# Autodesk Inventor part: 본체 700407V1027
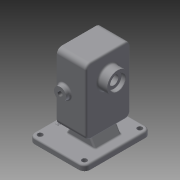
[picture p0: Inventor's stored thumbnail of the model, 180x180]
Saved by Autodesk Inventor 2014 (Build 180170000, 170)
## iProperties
Created: 2020-04
Part Number: 본체 700407V1027
Material: 일반
Document SubType Name: Modeling
Designer: kh
Density: 1 g/cm^3
Appearance: 기본값
Mass: 545.034 g
Surface Area: 818.916 cm^2
Volume: 545.034 cm^3
Author: kh
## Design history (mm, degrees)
sketch "스케치1"
  geometry: L1 (-50, -60)-(50, -60); L2 (50, -60)-(50, 60); L3 (50, 60)-(-50, 60); L4 (-50, 60)-(-50, -60); L5 (-50, -60)-(50, 60); L6 (50, -60)-(-50, 60); 1 further point
  constraints: 12 end point, 2 midpoint, 2 parallel, 1 horizontal, 1 perpendicular
  dimensions: "d0" = 100 distance of L2.end L3.end; "d1" = 120 distance of L3.end L1.start
extrude "돌출1" new body sketch "스케치1" distance "d2" = 10; taper "d3" = 0 deg
node "작업 평면2"
  node "작업 평면1"
sketch "스케치2"
  geometry: L1 (20, 150)-(100, 150); L2 (100, 150)-(100, 30); L3 (100, 30)-(20, 30); L4 (20, 30)-(20, 150); L5 (120, 0)-(0, 0) reference; L6 (20, 90)-(100, 90); L7 (60, 0)-(60, 50.718)
  constraints: 12 end point, 2 midpoint, 2 parallel, 2 perpendicular, 1 horizontal, 1 other
  dimensions: "d5" = 80 distance of L1.start L1.end; "d6" = 150 distance between parallel lines of L5 L1; "d7" = 90 distance from line of L7.start L6
extrude "돌출2" join sketch "스케치2" distance "d8" = 53; taper "d9" = 0 deg
sketch "스케치3"
  geometry: L1 (150, 20)-(150, 100) reference; L2 (150, 100)-(30, 100) reference; L3 (30, 100)-(30, 20) reference; L4 (30, 20)-(150, 20) reference; L5 (112, 60)-(68, 60); L6 (112, 36)-(68, 36); L7 (68, 84)-(112, 84); L8 (150, 100)-(30, 100) reference; L9 (90, 100)-(90, 20); A1 r 24 centre (112, 60) between (112, 36) and (112, 84); A2 r 24 centre (68, 60) between (68, 84) and (68, 36); 3 further points
  constraints: 10 end point, 4 midpoint, 4 point on circle, 4 tangent, 2 centre point, 2 parallel, 1 coincident
  dimensions: "d10" = 92 dimension on A2 A1; "d11" = 24 radius of A1
extrude "돌출3" cut sketch "스케치3" distance "d12" = 29; taper "d13" = 0 deg
sketch "스케치4"
  geometry: L1 (-150, 20)-(-150, 100) reference; L2 (-30, 20)-(-150, 20) reference; L3 (-30, 100)-(-30, 20) reference; L4 (-150, 100)-(-30, 100) reference; L5 (-150, 60)-(-30, 60); L6 (-30, 100)-(-30, 20) reference; L7 (-90, 20)-(-90, 118.269); L8 (-150, 100)-(-30, 100) reference; C1 r 19 at (-112, 60); 1 further point
  constraints: 4 end point, 3 midpoint, 1 centre point, 1 perpendicular, 1 point on line
  dimensions: "d14" = 38 diameter of C1; "d15" = 22 distance from line of L7 C1.centre
extrude "돌출4" join sketch "스케치4" distance "d16" = 17; taper "d17" = 0 deg
sketch "스케치5"
  geometry: L1 (112, 36)-(68, 36) reference; L2 (68, 84)-(112, 84) reference; A1 r 24 centre (112, 60) between (112, 36) and (112, 84) reference; A2 r 24 centre (68, 60) between (68, 84) and (68, 36) reference; 1 further point
hole "구멍1" sketch "스케치5" at (112, 60), (68, 60) diameter "d18" = 25; stored, may be unused: countersink angle "d22" = 90 deg, drill point angle "d24" = 0 deg; dims "d19" = 6, "d20" = 4, "d21" = 2, "d23" = 15
sketch "스케치6"
  geometry: C1 r 12.5 at (0, 0) reference; C2 r 8.5 at (0, 0); 1 further point
  constraints: 1 centre point, 1 coincident
  dimensions: "d25" = 17 diameter of C2
extrude "돌출5" cut sketch "스케치6" stored distance "d26" = 17; taper "d27" = 0 deg
sketch "스케치7"
  geometry: L1 (-33, 30)-(20, 30) reference; L2 (50, 10)-(-50, 10) reference; L3 (-21.453, 30)-(-33, 10); L4 (-50, 10)-(50, 10) reference; L5 (8.453, 30)-(20, 10); L6 (8.453, 30)-(-21.453, 30); L7 (-33, 30)-(20, 30) reference; L8 (20, 10)-(-33, 10); 1 further point
  constraints: 8 end point, 4 point on line, 2 collinear
  dimensions: "d28" = 60 deg angle of L4 L3; "d29" = 60 deg angle of L2 L5; "d30" = 17 distance of L2.end L3.end; "d31" = 53 distance of L5.end L3.end
extrude "돌출6" join sketch "스케치7" stored distance "d32" = 48; taper "d33" = 0 deg
sketch "스케치8"
  geometry: L1 (0, 120)-(-53, 120) reference; L2 (-53, 0)-(-53, 120) reference; L3 (-83, -30)-(17, -30) reference; C1 r 11 at (-39, 60); 1 further point
  constraints: 1 centre point
  dimensions: "d34" = 22 diameter of C1; "d35" = 90 distance from line of L3 C1.centre; "d37" = 14 distance from line of L2 C1.centre
extrude "돌출7" join sketch "스케치8" distance "d38" = 8; taper "d39" = 0 deg
hole "구멍2" diameter "d42" = 8.917; stored, may be unused: countersink angle "d46" = 90 deg, drill point angle "d48" = 0 deg; dims "d40" = 10, "d41" = 10, "d43" = 6, "d44" = 4, "d45" = 2, "d47" = 15
fillet "모깎기1" dims "d49" = 9
fillet "모깎기2" dims "d50" = 10
sketch "스케치9"
  geometry: A1 r 10 centre (-40, 50) between (-40, 60) and (-50, 50) reference; A2 r 10 centre (40, 50) between (50, 50) and (40, 60) reference; A3 r 10 centre (40, -50) between (40, -60) and (50, -50) reference; A4 r 10 centre (-40, -50) between (-50, -50) and (-40, -60) reference; 1 further point
hole "구멍3" sketch "스케치9" at (-40, 50), (-40, -50), (40, 50), (40, -50) diameter "d51" = 9; stored, may be unused: countersink angle "d55" = 90 deg, drill point angle "d57" = 0 deg; dims "d52" = 6, "d53" = 4, "d54" = 2, "d56" = 15
fillet "모깎기3" dims "d58" = 3
fillet "모깎기4" dims "d59" = 3
chamfer "모따기1" distance "d60" = 1; stored, may be unused: second distance "d61" = 2, angle "d62" = 45 deg
sketch "스케치10"
  geometry: C1 r 8.5 at (0, 0) reference; C2 r 14 at (0, 0); 1 further point
  constraints: 1 centre point, 1 coincident
  dimensions: "d63" = 28 diameter of C2
extrude "돌출8" cut sketch "스케치10" distance "d64" = 7.3; taper "d65" = 0 deg
chamfer "모따기2" distance "d66" = 0.7; stored, may be unused: second distance "d67" = 2, angle "d68" = 30 deg
fillet "모깎기5" dims "d69" = 0.5
fillet "모깎기6" dims "d70" = 3
sketch "스케치11"
  geometry: L1 (-15.982, 8.125)-(-15.982, -8.125); L2 (-15.982, -8.125)-(-64.018, -8.125); L3 (-64.018, -8.125)-(-64.018, 8.125); L4 (-64.018, 8.125)-(-15.982, 8.125); L5 (-15.982, -8.125)-(-64.018, 8.125); L6 (-15.982, 8.125)-(-64.018, -8.125); L7 (-50, 50)-(-50, -50) reference; L8 (40, 60)-(-40, 60) reference; 2 further points
  constraints: 4 end point, 1 midpoint, 2 other
  dimensions: "d71" = 10 distance from line of L7 point (-40, 0); "d72" = 60 distance from line of L8 point (-40, 0)
feature "엠보싱1" sketch "스케치11" dims "d0" = 100, "d1" = 120, "d73" = 0.5, "d74" = 0
sketch "스케치12"
  geometry: L1 (150, 29)-(150, 91) reference; L2 (150, 60)-(30, 60); L3 (30, 91)-(30, 29) reference; L4 (141, 91)-(39, 91); L5 (39, 91)-(39, 29); L6 (39, 29)-(141, 29); L7 (141, 29)-(141, 91); L8 (90, 91)-(90, 29); L9 (112, 91)-(112, 29); L10 (68, 91)-(68, 29); L11 (0, 110)-(0, 10) reference; A1 r 9 centre (141, 91) between (150, 91) and (141, 100) reference; A2 r 9 centre (141, 29) between (141, 20) and (150, 29) reference; A3 r 9 centre (39, 91) between (39, 100) and (30, 91) reference; A4 r 9 centre (39, 29) between (30, 29) and (39, 20) reference; 9 further points
  constraints: 16 end point, 8 coincident, 4 midpoint, 4 point on line, 3 perpendicular, 2 parallel, 1 horizontal, 2 other
  dimensions: "d84" = 62 distance of L6.end L4.start; "d85" = 102 distance between parallel lines of L5 L7; "d86" = 44 distance between parallel lines of L10 L9; "d87" = 90 distance between parallel lines of L11 L8
hole "구멍5" sketch "스케치12" at (141, 91), (141, 29), (112, 29), (112, 91), (68, 91), (68, 29), (39, 91), (39, 29) diameter "d88" = 4.134; stored, may be unused: countersink angle "d92" = 90 deg, drill point angle "d94" = 118 deg; dims "d89" = 10, "d90" = 4, "d91" = 2, "d93" = 12
node "솔리드1"
mirror "대칭1"
node "투영된 루프1"
node "투영된 루프2"
node "투영된 루프3"
node "투영된 루프4"
other parameters: "d4" = -17
